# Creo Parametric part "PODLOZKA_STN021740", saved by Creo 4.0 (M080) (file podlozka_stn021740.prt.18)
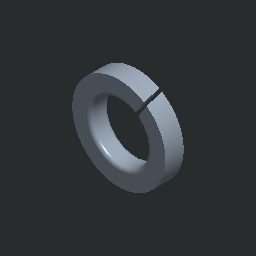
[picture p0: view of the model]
Units: Custom; MM, KILOGRAM, SECS
Materials in the file: OCEL_N

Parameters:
  MFG_WP_MATERIAL = "OCEL"
  NAZOV = "PODLOZKA_STN021740"
  NORMA = "STN 02 1740"
  PTC_MATERIAL_NAME = "OCEL_N"

Other parameters: HMOTNOST, HUSTOTA

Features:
  1. datum plane "DTM1"
  2. datum plane "DTM4"
  3. round
  4. datum plane "DTM7"

Layers: 1, 2, 3, 4, 5, 6, 7, 8, 9, 10, 11, 12, 13, 14, 15, 16, 17, 18, 19, 20, 21, 22, 23, 24, 25, 26, 27, 28, 29, 30, 31, 32

Family table entries: GENERIC, PODLOZKA_3, PODLOZKA_STN021740, value(d_val), value(i_val), PODLOZKA_3_5, PODLOZKA_STN021740, PODLOZKA_4, PODLOZKA_STN021740, PODLOZKA_5, PODLOZKA_STN021740, PODLOZKA_6, PODLOZKA_STN021740, PODLOZKA_7, PODLOZKA_STN021740, PODLOZKA_8, PODLOZKA_STN021740, PODLOZKA_10, PODLOZKA_STN021740, PODLOZKA_12, PODLOZKA_STN021740, PODLOZKA_14, PODLOZKA_STN021740, PODLOZKA_16, PODLOZKA_STN021740, PODLOZKA_18, PODLOZKA_STN021740, PODLOZKA_20, PODLOZKA_STN021740, PODLOZKA_22, PODLOZKA_STN021740, PODLOZKA_24, PODLOZKA_STN021740, PODLOZKA_27, PODLOZKA_STN021740, PODLOZKA_30, PODLOZKA_STN021740, PODLOZKA_33, PODLOZKA_STN021740, PODLOZKA_36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

Surfaces: 4 plane, 4 torus, 2 cylinder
